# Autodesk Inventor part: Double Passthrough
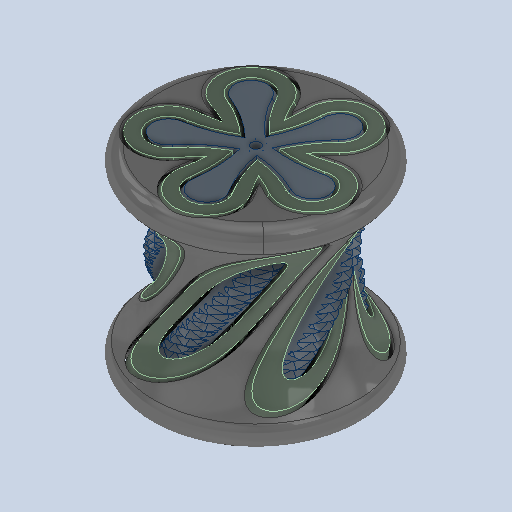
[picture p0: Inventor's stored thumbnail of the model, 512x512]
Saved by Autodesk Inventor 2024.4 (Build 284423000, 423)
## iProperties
Created: 2025-11
Part Number: Double Passthrough
Material: Generic
Document SubType Name: Modeling
Designer: AdminForWorker
Density: 1 g/cm^3
Appearance: Default
Title: Double Passthrough v14
Author: AdminForWorker
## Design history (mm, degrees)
feature "Inner"
feature "Middle"
feature "Outer"
body "Solid1"
body "Solid2"
body "Solid3"
